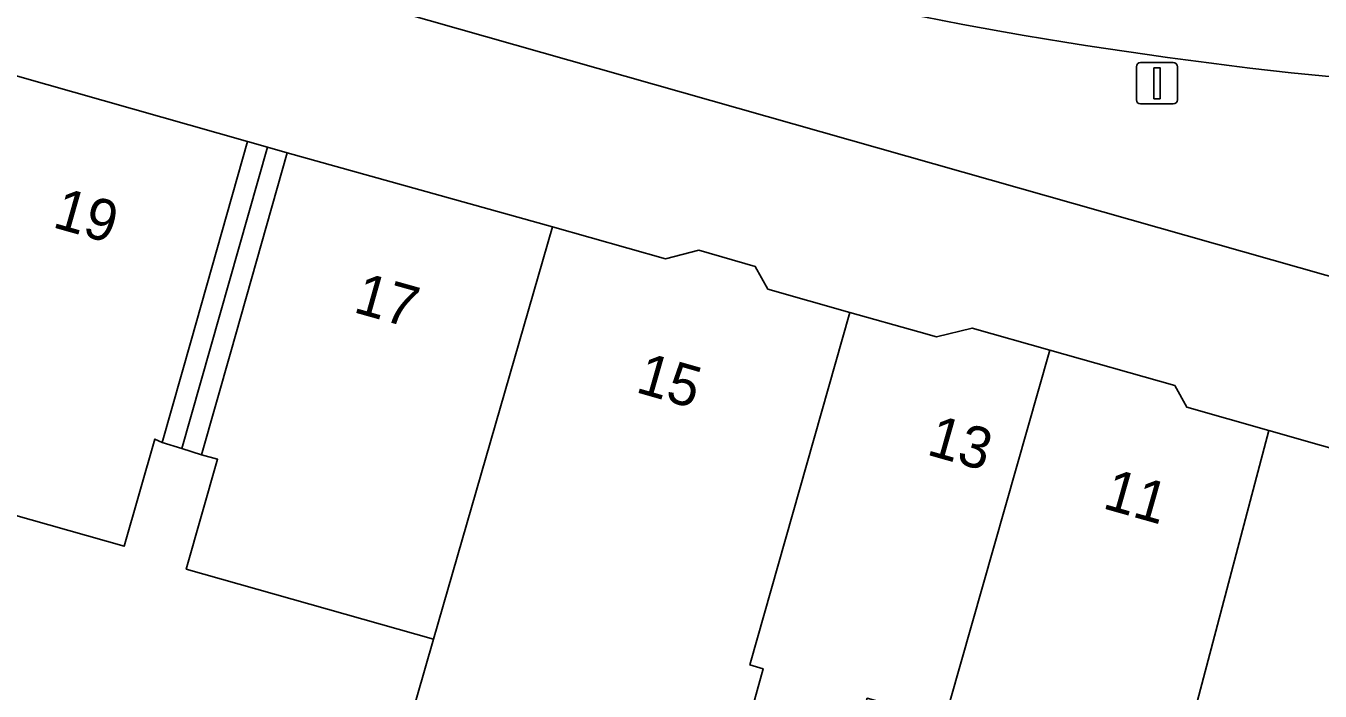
# Model space of a CAD drawing. Extents: x 158086 to 159499, y 382904 to 383981.
# Drawn here: x 158866.21 to 158897.48, y 383257.98 to 383274.05 of the extents above; entities that cross this region are included whole.
import ezdxf

# ---------------------------------------------------------------- set-up
doc = ezdxf.new("R2010")
doc.units = 0
for name, color, linetype in [('IMGEO_Erf', 7, 'Continuous'), ('IMGEO_Lichtmast', 7, 'Continuous'), ('IMGEO_Pand', 7, 'Continuous'), ('IMGEO_Pand_nummerreeks', 7, 'Continuous'), ('IMGEO_Pand_overbouw', 7, 'Continuous'), ('IMGEO_Parkeervlak_open', 7, 'Continuous'), ('IMGEO_Voetpad_open', 7, 'Continuous')]:
    doc.layers.add(name, color=color, linetype=linetype)

msp = doc.modelspace()

# ---------------------------------------------------------------- linework, layer by layer
at = {"layer": 'IMGEO_Erf'}
for points in [[(158903.057, 383266.48), (158866.482, 383276.877), (158865.516, 383273.825), (158865.294, 383273.04), (158871.564, 383271.26), (158870.203, 383266.449), (158869.506, 383263.987), (158869.329, 383264.068), (158868.583, 383261.477), (158862.688, 383263.145), (158859.076, 383250)], [(158875.237, 383256.376), (158876.059, 383259.228), (158870.087, 383260.923), (158870.841, 383263.58), (158870.456, 383263.689), (158871.161, 383266.178), (158872.526, 383270.987), (158878.93, 383269.192), (158881.661, 383268.426), (158882.465, 383268.629), (158883.83, 383268.241), (158884.137, 383267.691), (158886.119, 383267.128), (158887.783, 383266.655), (158888.208, 383266.534), (158889.07, 383266.751), (158890.944, 383266.219), (158893.965, 383265.362), (158894.257, 383264.838), (158896.238, 383264.276), (158898.786, 383263.553)]]:
    msp.add_lwpolyline(points, dxfattribs=at)
at = {"layer": 'IMGEO_Lichtmast'}
for p, q in [((158893.04, 383272.265), (158893.04, 383273.065)), ((158893.04, 383273.065), (158893.04, 383272.265)), ((158893.14, 383273.165), (158893.93, 383273.165)), ((158893.93, 383273.165), (158893.14, 383273.165)), ((158894.03, 383273.065), (158894.03, 383272.265)), ((158894.03, 383272.265), (158894.03, 383273.065)), ((158893.93, 383272.165), (158893.14, 383272.165)), ((158893.14, 383272.165), (158893.93, 383272.165))]:
    msp.add_line(p, q, dxfattribs=at)
msp.add_lwpolyline([(158893.46, 383273.04), (158893.61, 383273.04), (158893.61, 383272.29), (158893.46, 383272.29), (158893.46, 383273.04)], dxfattribs=at)
for centre, start, end in [((158893.14, 383273.065), 90, 180), ((158893.14, 383273.065), 90, 180), ((158893.93, 383273.065), 0, 90), ((158893.93, 383273.065), 360, 90), ((158893.14, 383272.265), 180, 270), ((158893.14, 383272.265), 180, 270), ((158893.93, 383272.265), 270, 0), ((158893.93, 383272.265), 270, 0)]:
    msp.add_arc(centre, 0.1, start, end, dxfattribs=at)
at = {"layer": 'IMGEO_Pand'}
for points in [[(158865.294, 383273.04), (158863.437, 383265.794), (158862.741, 383263.337), (158862.688, 383263.145), (158868.583, 383261.477), (158869.329, 383264.068), (158869.506, 383263.987), (158870.203, 383266.449), (158871.564, 383271.26)], [(158878.93, 383269.192), (158872.526, 383270.987), (158871.161, 383266.178), (158870.456, 383263.689), (158870.841, 383263.58), (158870.087, 383260.923), (158876.059, 383259.228)], [(158886.119, 383267.128), (158884.137, 383267.691), (158883.83, 383268.241), (158882.465, 383268.629), (158881.661, 383268.426), (158878.93, 383269.192), (158876.059, 383259.228), (158875.237, 383256.376), (158874.663, 383254.354), (158878.046, 383253.393), (158879.201, 383257.464), (158883.4, 383256.272), (158884.025, 383258.517), (158883.702, 383258.609)], [(158890.944, 383266.219), (158889.07, 383266.751), (158888.208, 383266.534), (158887.783, 383266.655), (158886.119, 383267.128), (158883.702, 383258.609), (158884.025, 383258.517), (158883.4, 383256.272), (158882.592, 383253.369), (158885.075, 383252.657), (158885.771, 383255.11), (158886.536, 383257.805), (158888.434, 383257.266), (158888.526, 383257.692)], [(158892.628, 383250.614), (158896.238, 383264.276), (158894.257, 383264.838), (158893.965, 383265.362), (158890.944, 383266.219), (158888.526, 383257.692), (158888.434, 383257.266), (158891.613, 383256.364), (158890.178, 383251.309)], [(158901.962, 383262.629), (158900.931, 383262.921), (158900.632, 383263.458), (158899.586, 383263.755), (158898.786, 383263.553), (158896.238, 383264.276), (158892.628, 383250.614), (158894.792, 383250), (158895.511, 383249.796), (158895.569, 383250), (158896.949, 383254.861), (158899.596, 383254.066), (158899.797, 383254.006), (158899.953, 383254.553), (158899.691, 383254.627)]]:
    msp.add_lwpolyline(points, close=True, dxfattribs=at)
at = {"layer": 'IMGEO_Pand_overbouw'}
for points in [[(158871.564, 383271.26), (158870.203, 383266.449), (158869.506, 383263.987), (158869.981, 383263.838), (158872.045, 383271.124)], [(158872.526, 383270.987), (158872.045, 383271.124), (158869.981, 383263.838), (158870.456, 383263.689), (158871.161, 383266.178)]]:
    msp.add_lwpolyline(points, close=True, dxfattribs=at)
at = {"layer": 'IMGEO_Parkeervlak_open'}
msp.add_arc((158908.198, 383378.076), 105.774, 256.47029, 265.15878, dxfattribs=at)
at = {"layer": 'IMGEO_Voetpad_open'}
msp.add_lwpolyline([(158790.372, 383295.088), (158799.862, 383292.403), (158806.883, 383290.416), (158813.942, 383288.419), (158815.192, 383288.065), (158822.379, 383286.031), (158829.444, 383284.032), (158835.697, 383282.263), (158839.065, 383281.31), (158845.937, 383279.365), (158852.621, 383277.474), (158859.187, 383275.616), (158865.516, 383273.825), (158866.482, 383276.877), (158903.057, 383266.48)], dxfattribs=at)
msp.add_arc((158908.198, 383378.076), 105.774, 256.47029, 265.15878, dxfattribs=at)

# ---------------------------------------------------------------- texts
at = {"layer": 'IMGEO_Pand_nummerreeks'}
for s, rotation, p in [('19', 344.1512, (158866.826, 383269.195)), ('17', 344.3353, (158874.093, 383267.142)), ('15', 343.9801, (158880.912, 383265.21)), ('13', 344.1652, (158887.944, 383263.7)), ('11', 344.1586, (158892.193, 383262.404))]:
    msp.add_text(s, height=1, rotation=rotation, dxfattribs=at).set_placement(p)

doc.saveas('drawing.dxf')
